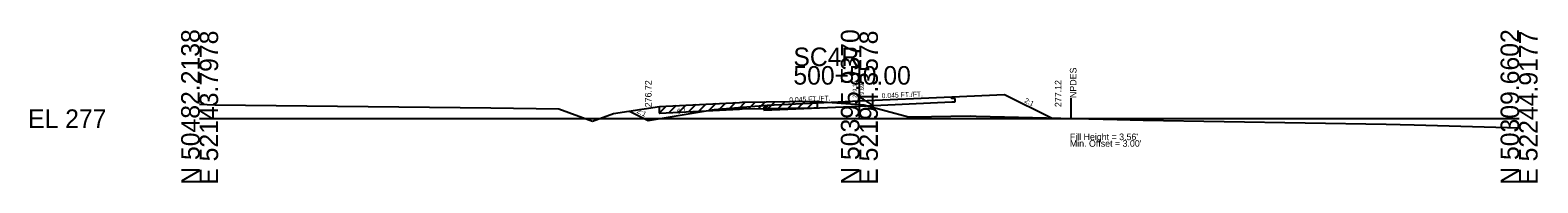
# Model space of a CAD drawing. Extents: x 7498 to 13027, y 90095 to 109625.
# Drawn here: x 8498.3 to 8726.8, y 90595.5 to 90618.5 of the extents above; entities that cross this region are included whole.
import ezdxf

# ---------------------------------------------------------------- set-up
doc = ezdxf.new("R2010")
doc.units = 0
for name, color, linetype in [('Level 10', 7, 'Continuous'), ('Level 11', 7, 'Continuous'), ('Level 12', 7, 'Continuous'), ('Level 32', 7, 'Continuous'), ('Level 33', 7, 'Continuous'), ('Level 50', 7, 'Continuous'), ('Level 55', 7, 'Continuous'), ('Level 59', 7, 'Continuous'), ('Level 6', 7, 'Continuous'), ('Level 60', 7, 'Continuous'), ('Level 61', 7, 'Continuous'), ('Level 63', 7, 'Continuous'), ('Level 7', 7, 'Continuous')]:
    doc.layers.add(name, color=color, linetype=linetype)

msp = doc.modelspace()

# ---------------------------------------------------------------- linework, layer by layer
at = {"layer": 'Level 11'}
for p, q in [((8637.99, 90608.17), (8637.99, 90608.47)), ((8638.49, 90608.2), (8637.99, 90608.17)), ((8637.99, 90607.69), (8638.49, 90607.72)), ((8638.49, 90607.72), (8638.49, 90608.2))]:
    msp.add_line(p, q, dxfattribs=at)
at = {"layer": 'Level 12'}
for p, q in [((8609.49, 90606.43), (8623.99, 90607.06)), ((8609.99, 90607.21), (8609.99, 90606.91)), ((8623.99, 90607.06), (8637.99, 90607.69)), ((8609.99, 90606.91), (8609.49, 90606.91)), ((8609.49, 90606.91), (8609.49, 90606.43))]:
    msp.add_line(p, q, dxfattribs=at)
at = {"layer": 'Level 55'}
msp.add_line((8656.11, 90605.28), (8656.11, 90608.28), dxfattribs=at)
at = {"layer": 'Level 59'}
for p, q in [((8609.99, 90607.21), (8623.99, 90607.84)), ((8623.99, 90607.84), (8637.99, 90608.47))]:
    msp.add_line(p, q, dxfattribs=at)
at = {"layer": 'Level 6'}
for p, q in [((8601.99, 90606.55), (8609.99, 90607.21)), ((8637.99, 90608.47), (8645.99, 90608.83))]:
    msp.add_line(p, q, dxfattribs=at)
at = {"layer": 'Level 60'}
for p, q in [((8523.99, 90607.37), (8526.29, 90607.27)), ((8526.29, 90607.27), (8568.12, 90606.8)), ((8586.74, 90605.92), (8593.72, 90607.01)), ((8593.72, 90607.01), (8605.84, 90607.61)), ((8605.84, 90607.61), (8606.21, 90607.63)), ((8606.21, 90607.63), (8617.1, 90607.8)), ((8617.1, 90607.8), (8617.8, 90607.78)), ((8617.8, 90607.78), (8623.99, 90607.31)), ((8623.99, 90607.31), (8624.67, 90607.25)), ((8624.67, 90607.25), (8631.43, 90605.43)), ((8568.12, 90606.8), (8578.44, 90606.67)), ((8578.44, 90606.67), (8583.55, 90604.8)), ((8583.55, 90604.8), (8586.74, 90605.92)), ((8631.43, 90605.43), (8631.94, 90605.44)), ((8631.94, 90605.44), (8640.85, 90605.59)), ((8640.85, 90605.59), (8641.68, 90605.56)), ((8641.68, 90605.56), (8663.07, 90605.03)), ((8663.07, 90605.03), (8667.03, 90604.95)), ((8667.03, 90604.95), (8703.86, 90604.34)), ((8703.86, 90604.34), (8708.09, 90604.21)), ((8708.09, 90604.21), (8723.99, 90603.76))]:
    msp.add_line(p, q, dxfattribs=at)
at = {"layer": 'Level 61'}
for p, q in [((8594.71, 90607.06), (8593.65, 90606)), ((8593.65, 90607), (8593.65, 90606)), ((8596.2, 90607.14), (8595.15, 90606.08)), ((8597.71, 90607.21), (8596.65, 90606.16)), ((8599.21, 90607.29), (8598.16, 90606.23)), ((8600.71, 90607.36), (8599.66, 90606.31)), ((8602.21, 90607.43), (8601.16, 90606.38)), ((8603.72, 90607.51), (8602.66, 90606.46)), ((8605.22, 90607.58), (8604.16, 90606.53)), ((8606.7, 90607.64), (8605.67, 90606.6)), ((8608.19, 90607.66), (8607.17, 90606.64)), ((8609.69, 90607.68), (8608.67, 90606.67)), ((8611.19, 90607.71), (8610.17, 90606.69)), ((8612.69, 90607.73), (8611.67, 90606.72)), ((8614.19, 90607.75), (8613.18, 90606.74)), ((8615.7, 90607.78), (8614.68, 90606.76)), ((8617.19, 90607.8), (8616.18, 90606.79)), ((8617.64, 90606.78), (8617.64, 90607.78)), ((8593.65, 90606), (8593.72, 90606.01)), ((8593.72, 90606.01), (8605.84, 90606.61)), ((8605.84, 90606.61), (8606.21, 90606.63)), ((8606.21, 90606.63), (8617.1, 90606.8)), ((8617.1, 90606.8), (8617.64, 90606.78))]:
    msp.add_line(p, q, dxfattribs=at)
at = {"layer": 'Level 63'}
for p, q in [((8623.99, 90605.16), (8623.99, 90613.11)), ((8523.99, 90605.16), (8623.99, 90605.16)), ((8623.99, 90605.16), (8723.99, 90605.16))]:
    msp.add_line(p, q, dxfattribs=at)
at = {"layer": 'Level 7'}
for p, q in [((8645.99, 90608.83), (8653.11, 90605.28)), ((8589.16, 90606.3), (8591.99, 90604.88)), ((8591.99, 90604.88), (8601.99, 90606.55))]:
    msp.add_line(p, q, dxfattribs=at)

# ---------------------------------------------------------------- texts
at = {"layer": 'Level 10'}
msp.add_text('279.15', height=0.6, rotation=90, dxfattribs=at).set_placement((8623.59, 90608.31))
at = {"layer": 'Level 32'}
for s, rotation, p in [('0.045 FT./FT.', 2.5766, (8627.38, 90608.25)), ('0.045 FT./FT.', 2.5766, (8613.38, 90607.62)), ('2:1', 333.435, (8648.93, 90607.66)), ('2:1', 333.435, (8590.18, 90606.07)), ('6:1', 9.4623, (8596.43, 90605.87))]:
    msp.add_text(s, height=0.75, rotation=rotation, dxfattribs=at).set_placement(p)
at = {"layer": 'Level 33'}
for s, p in [('276.72', (8592.49, 90606.88)), ('277.12', (8654.62, 90606.91))]:
    msp.add_text(s, height=1, rotation=90, dxfattribs=at).set_placement(p)
at = {"layer": 'Level 50'}
msp.add_text(' NPDES', height=1, rotation=90, dxfattribs=at).set_placement((8656.9, 90607.91))
for s, p in [("Fill Height = 3.56' ", (8655.9, 90601.91)), ("Min. Offset = 3.00' ", (8655.9, 90600.91))]:
    msp.add_text(s, height=1, dxfattribs=at).set_placement(p)
at = {"layer": 'Level 59'}
msp.add_text(' 279.69', height=0.6, rotation=90, dxfattribs=at).set_placement((8624.67, 90607.63))
at = {"layer": 'Level 63'}
for s, p in [('N 50482.2138', (8523.99, 90595.16)), ('N 50395.9370', (8623.99, 90595.16)), ('N 50309.6602', (8723.99, 90595.16)), ('E 52143.7978', (8526.79, 90595.16)), ('E 52194.3578', (8626.79, 90595.16)), ('E 52244.9177', (8726.79, 90595.16))]:
    msp.add_text(s, height=2.8, rotation=90, dxfattribs=at).set_placement(p)
for s, p in [('SC4R', (8613.99, 90613.11)), ('500+50.00', (8613.99, 90610.31)), ('EL 277', (8497.99, 90603.76))]:
    msp.add_text(s, height=2.8, dxfattribs=at).set_placement(p)

doc.saveas('drawing.dxf')
